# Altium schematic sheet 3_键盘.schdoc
size 431 x 309 mm; Symbol: Sheet-Symbol_A3; Device: Sheet-Symbol_A3; Company: 嘉立创EDA; Version: V1.0; Page Size: A3; @Project Name: 电容触摸键盘-第二验证板; @Page Count: 3; @Update Date: 2024-11-03; @Create Date: 2024-11-03; @Schematic Name: Schematic1; @Page No: 3; @Page Name: 键盘; Title Block Position: 3; Width: 1170; Height: 825; Region Start: 1; X Region Count: 6; Y Region Count: 4; Blade Width: 10; @Board Name: Board1; @Create Time: 12:21:13; @Update Time: 12:46:31
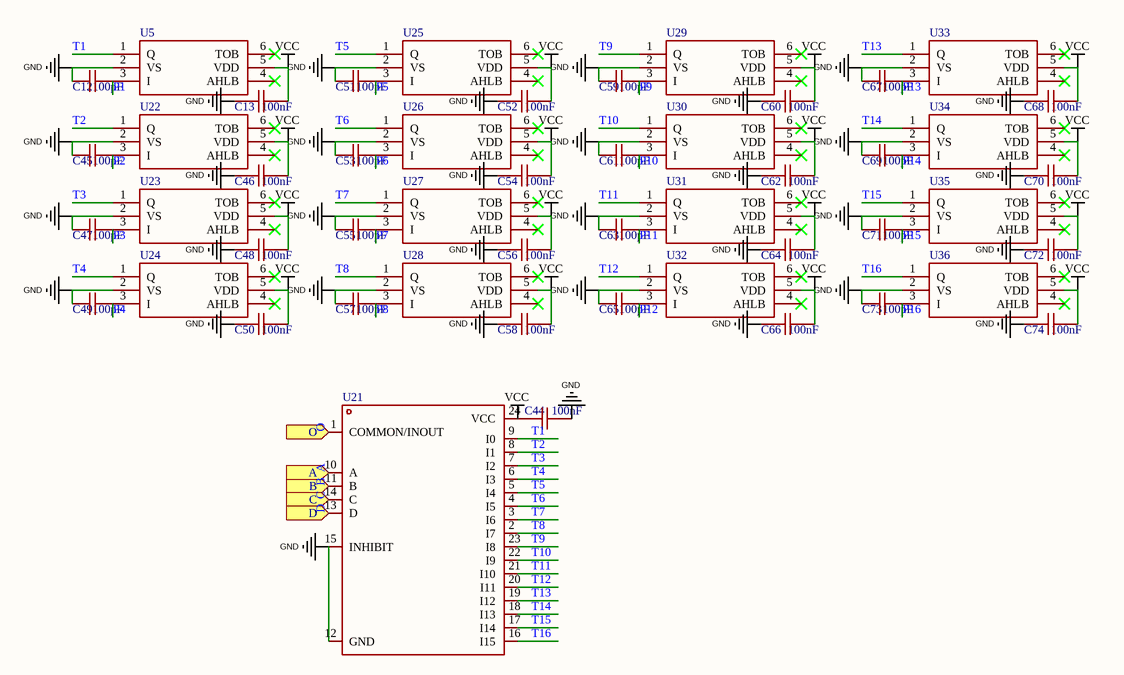
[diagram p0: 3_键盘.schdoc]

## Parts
C12  100pF  [C0603]
C13  100nF  [C0603]
C44  100nF  [C0603]
C45  100pF  [C0603]
C46  100nF  [C0603]
C47  100pF  [C0603]
C48  100nF  [C0603]
C49  100pF  [C0603]
C50  100nF  [C0603]
C51  100pF  [C0603]
C52  100nF  [C0603]
C53  100pF  [C0603]
C54  100nF  [C0603]
C55  100pF  [C0603]
C56  100nF  [C0603]
C57  100pF  [C0603]
C58  100nF  [C0603]
C59  100pF  [C0603]
C60  100nF  [C0603]
C61  100pF  [C0603]
C62  100nF  [C0603]
C63  100pF  [C0603]
C64  100nF  [C0603]
C65  100pF  [C0603]
C66  100nF  [C0603]
C67  100pF  [C0603]
C68  100nF  [C0603]
C69  100pF  [C0603]
C70  100nF  [C0603]
C71  100pF  [C0603]
C72  100nF  [C0603]
C73  100pF  [C0603]
C74  100nF  [C0603]
U5  TTP233D-HA6  [SOT-23-6_L2.9-W1.6-P0.95-LS2.8-BR]  (value not drawn)
U21  CD4067BPWG4  [TSSOP-24_L7.8-W4.4-P0.65-LS6.4-BL_1]  (value not drawn)
U22  TTP233D-HA6  [SOT-23-6_L2.9-W1.6-P0.95-LS2.8-BR]  (value not drawn)
U23  TTP233D-HA6  [SOT-23-6_L2.9-W1.6-P0.95-LS2.8-BR]  (value not drawn)
U24  TTP233D-HA6  [SOT-23-6_L2.9-W1.6-P0.95-LS2.8-BR]  (value not drawn)
U25  TTP233D-HA6  [SOT-23-6_L2.9-W1.6-P0.95-LS2.8-BR]  (value not drawn)
U26  TTP233D-HA6  [SOT-23-6_L2.9-W1.6-P0.95-LS2.8-BR]  (value not drawn)
U27  TTP233D-HA6  [SOT-23-6_L2.9-W1.6-P0.95-LS2.8-BR]  (value not drawn)
U28  TTP233D-HA6  [SOT-23-6_L2.9-W1.6-P0.95-LS2.8-BR]  (value not drawn)
U29  TTP233D-HA6  [SOT-23-6_L2.9-W1.6-P0.95-LS2.8-BR]  (value not drawn)
U30  TTP233D-HA6  [SOT-23-6_L2.9-W1.6-P0.95-LS2.8-BR]  (value not drawn)
U31  TTP233D-HA6  [SOT-23-6_L2.9-W1.6-P0.95-LS2.8-BR]  (value not drawn)
U32  TTP233D-HA6  [SOT-23-6_L2.9-W1.6-P0.95-LS2.8-BR]  (value not drawn)
U33  TTP233D-HA6  [SOT-23-6_L2.9-W1.6-P0.95-LS2.8-BR]  (value not drawn)
U34  TTP233D-HA6  [SOT-23-6_L2.9-W1.6-P0.95-LS2.8-BR]  (value not drawn)
U35  TTP233D-HA6  [SOT-23-6_L2.9-W1.6-P0.95-LS2.8-BR]  (value not drawn)
U36  TTP233D-HA6  [SOT-23-6_L2.9-W1.6-P0.95-LS2.8-BR]  (value not drawn)

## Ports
A (in), B (in), C (in), D (in), O (in)

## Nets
GND: C12.1 C13.2 C44.2 C45.1 C46.2 C47.1 C48.2 C49.1 C50.2 C51.1 C52.2 C53.1 C54.2 C55.1 C56.2 C57.1 C58.2 C59.1 C60.2 C61.1 C62.2 C63.1 C64.2 C65.1 C66.2 C67.1 C68.2 C69.1 C70.2 C71.1 C72.2 C73.1 C74.2 U5.2(VS) U21.12(GND) U21.15(INHIBIT) U22.2(VS) U23.2(VS) U24.2(VS) U25.2(VS) U26.2(VS) U27.2(VS) U28.2(VS) U29.2(VS) U30.2(VS) U31.2(VS) U32.2(VS) U33.2(VS) U34.2(VS) U35.2(VS) U36.2(VS)
VCC: C13.1 C44.1 C46.1 C48.1 C50.1 C52.1 C54.1 C56.1 C58.1 C60.1 C62.1 C64.1 C66.1 C68.1 C70.1 C72.1 C74.1 U5.5(VDD) U21.24(VCC) U22.5(VDD) U23.5(VDD) U24.5(VDD) U25.5(VDD) U26.5(VDD) U27.5(VDD) U28.5(VDD) U29.5(VDD) U30.5(VDD) U31.5(VDD) U32.5(VDD) U33.5(VDD) U34.5(VDD) U35.5(VDD) U36.5(VDD)
A: U21.10(A) ; port A
B: U21.11(B) ; port B
C: U21.14(C) ; port C
D: U21.13(D) ; port D
O: U21.1(COMMON/INOUT) ; port O
P1: C12.2 U5.3(I)
P2: C45.2 U22.3(I)
P3: C47.2 U23.3(I)
P4: C49.2 U24.3(I)
P5: C51.2 U25.3(I)
P6: C53.2 U26.3(I)
P7: C55.2 U27.3(I)
P8: C57.2 U28.3(I)
P9: C59.2 U29.3(I)
P10: C61.2 U30.3(I)
P11: C63.2 U31.3(I)
P12: C65.2 U32.3(I)
P13: C67.2 U33.3(I)
P14: C69.2 U34.3(I)
P15: C71.2 U35.3(I)
P16: C73.2 U36.3(I)
T1: U5.1(Q) U21.9(I0)
T2: U21.8(I1) U22.1(Q)
T3: U21.7(I2) U23.1(Q)
T4: U21.6(I3) U24.1(Q)
T5: U21.5(I4) U25.1(Q)
T6: U21.4(I5) U26.1(Q)
T7: U21.3(I6) U27.1(Q)
T8: U21.2(I7) U28.1(Q)
T9: U21.23(I8) U29.1(Q)
T10: U21.22(I9) U30.1(Q)
T11: U21.21(I10) U31.1(Q)
T12: U21.20(I11) U32.1(Q)
T13: U21.19(I12) U33.1(Q)
T14: U21.18(I13) U34.1(Q)
T15: U21.17(I14) U35.1(Q)
T16: U21.16(I15) U36.1(Q)

Not connected (* = marked no-connect by the designer): U5 4(AHLB)* 6(TOB)*; U22 4(AHLB)* 6(TOB)*; U23 4(AHLB)* 6(TOB)*; U24 4(AHLB)* 6(TOB)*; U25 4(AHLB)* 6(TOB)*; U26 4(AHLB)* 6(TOB)*; U27 4(AHLB)* 6(TOB)*; U28 4(AHLB)* 6(TOB)*; U29 4(AHLB)* 6(TOB)*; U30 4(AHLB)* 6(TOB)*; U31 4(AHLB)* 6(TOB)*; U32 4(AHLB)* 6(TOB)*; U33 4(AHLB)* 6(TOB)*; U34 4(AHLB)* 6(TOB)*; U35 4(AHLB)* 6(TOB)*; U36 4(AHLB)* 6(TOB)*

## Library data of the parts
C12 C45 C47 C49 C51 C53 C55 C57 C59 C61 C63 C65 C67 C69 C71 C73 = CL10C101JB8NNNC: 容值:100pF;精度:±5%;额定电压:50V;材质(温度系数):C0G;; Manufacturer: SAMSUNG(三星); Add into BOM: yes; Tolerance: ±5%; Voltage Rated: 50V; Temperature Coefficient: C0G
C13 C44 C46 C48 C50 C52 C54 C56 C58 C60 C62 C64 C66 C68 C70 C72 C74 = CC0603KRX7R9BB104: 容值:100nF;精度:±10%;额定电压:50V;材质(温度系数):X7R;; Manufacturer: YAGEO(国巨); Add into BOM: yes; Tolerance: ±10%; Voltage Rated: 50V; Temperature Coefficient: X7R
U5 U22-U36 = TTP233D-HA6: 单按键触摸检测芯片; Manufacturer: TONTEK(通泰); Add into BOM: yes
U21 = CD4067BPWG4: Add into BOM: yes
